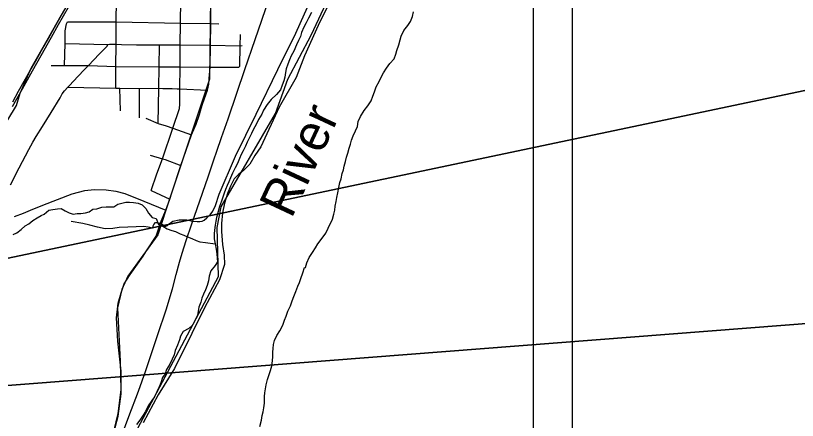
# Model space of a CAD drawing. Extents: x 0 to 34, y 0 to 22.
# Drawn here: x 7.567 to 9.58, y 17.57 to 18.613 of the extents above; entities that cross this region are included whole.
import ezdxf

# ---------------------------------------------------------------- set-up
doc = ezdxf.new("R2010")
doc.units = 0
for name, color, linetype in [('Default', 7, 'Continuous'), ('GM_X_City_Street', 7, 'Continuous'), ('GM_X_Corporation', 7, 'Continuous'), ('GM_X_County_Road', 7, 'Continuous'), ('GM_X_Major_River', 7, 'Continuous'), ('GM_X_Major_River_Text', 7, 'Continuous'), ('GM_X_Minor_River', 7, 'Continuous'), ('GM_X_Rail_Line', 7, 'Continuous'), ('GM_X_State_Route', 7, 'Continuous'), ('SC_Shading1', 7, 'Continuous'), ('SH_Cut_Line', 7, 'Continuous'), ('SH_Data', 7, 'Continuous')]:
    doc.layers.add(name, color=color, linetype=linetype)

msp = doc.modelspace()

# ---------------------------------------------------------------- linework, layer by layer
at = {"layer": 'Default'}
for p, q in [((8.3275, 18.5623), (8.3826, 18.6786)), ((8.2682, 18.4486), (8.3275, 18.5623)), ((8.2362, 18.3605), (8.2682, 18.4486)), ((8.0958, 18.1203), (8.2362, 18.3605)), ((8.0861, 18.0665), (8.0958, 18.1203)), ((8.0891, 17.94), (8.0861, 18.0665)), ((7.9735, 17.7219), (8.0891, 17.94)), ((7.8637, 17.5167), (7.9735, 17.7219))]:
    msp.add_line(p, q, dxfattribs=at)
at = {"layer": 'GM_X_City_Street'}
for p, q in [((8.288, 18.5677), (8.3375, 18.6773)), ((7.8259, 18.5966), (7.8266, 18.6535)), ((7.991, 18.5935), (7.9925, 18.6522)), ((7.6945, 18.5732), (7.6974, 18.5917)), ((7.6974, 18.5917), (7.7, 18.5966)), ((7.7, 18.5966), (7.8259, 18.5966)), ((7.8253, 18.5395), (7.8259, 18.5966)), ((7.8259, 18.5966), (7.991, 18.5935)), ((7.9905, 18.537), (7.991, 18.5935)), ((7.991, 18.5935), (8.0694, 18.5927)), ((8.0694, 18.5927), (8.0897, 18.5919)), ((7.6943, 18.5406), (7.6945, 18.5732)), ((8.2419, 18.4737), (8.288, 18.5677)), ((8.1454, 18.5352), (8.1456, 18.5644)), ((7.6922, 18.4838), (7.6943, 18.5406)), ((7.6943, 18.5406), (7.7683, 18.5393)), ((7.7683, 18.5393), (7.8045, 18.5385)), ((7.8246, 18.4817), (7.8253, 18.5395)), ((7.9362, 18.4811), (7.9369, 18.5377)), ((7.9909, 18.5241), (7.9905, 18.537)), ((8.0684, 18.5365), (8.1454, 18.5352)), ((8.1445, 18.4827), (8.1454, 18.5352)), ((8.1454, 18.5352), (8.1506, 18.5356)), ((7.9901, 18.4808), (7.9909, 18.5241)), ((7.658, 18.484), (7.6922, 18.4838)), ((7.6922, 18.4838), (7.7541, 18.4838)), ((7.7541, 18.4838), (7.8246, 18.4817)), ((7.8244, 18.4261), (7.8246, 18.4817)), ((7.8246, 18.4817), (7.9362, 18.4811)), ((7.9355, 18.4255), (7.9362, 18.4811)), ((7.9362, 18.4811), (7.9901, 18.4808)), ((7.9897, 18.424), (7.9901, 18.4808)), ((7.9901, 18.4808), (8.0675, 18.4799)), ((8.0675, 18.4799), (8.1417, 18.4799)), ((8.1417, 18.4799), (8.1445, 18.4827)), ((8.1865, 18.3591), (8.2419, 18.4737)), ((7.7011, 18.428), (7.8244, 18.4261)), ((7.8244, 18.4261), (7.835, 18.4259)), ((7.8364, 18.367), (7.835, 18.4259)), ((7.835, 18.4259), (7.8861, 18.4246)), ((7.8858, 18.3496), (7.8861, 18.4246)), ((7.8861, 18.4246), (7.9355, 18.4255)), ((7.9342, 18.3346), (7.9355, 18.4255)), ((7.9355, 18.4255), (7.9457, 18.4251)), ((7.9457, 18.4251), (7.9697, 18.4248)), ((7.9697, 18.4248), (7.983, 18.4243)), ((7.983, 18.4243), (7.9897, 18.424)), ((7.9893, 18.4014), (7.9897, 18.424)), ((7.9897, 18.424), (8.0606, 18.4209)), ((7.9884, 18.3732), (7.9895, 18.3841)), ((7.9895, 18.3841), (7.9893, 18.4014)), ((7.9712, 18.3226), (7.9884, 18.3732)), ((7.9018, 18.3487), (7.9342, 18.3346)), ((8.1332, 18.2503), (8.1865, 18.3591)), ((7.9342, 18.3346), (7.9543, 18.3286)), ((7.9543, 18.3286), (7.9712, 18.3226)), ((7.9446, 18.2437), (7.9712, 18.3226)), ((7.9712, 18.3226), (8.0201, 18.3053)), ((7.9131, 18.253), (7.9446, 18.2437)), ((7.9303, 18.2046), (7.9446, 18.2437)), ((7.9446, 18.2437), (7.9516, 18.2416)), ((8.0907, 18.1525), (8.1332, 18.2503)), ((7.9516, 18.2416), (7.9923, 18.2268)), ((7.9161, 18.1616), (7.9303, 18.2046)), ((7.9161, 18.1616), (7.9639, 18.1397)), ((8.0813, 18.1237), (8.0907, 18.1525)), ((8.0743, 18.1087), (8.0813, 18.1237)), ((8.0674, 18.0993), (8.0743, 18.1087)), ((7.7394, 18.0773), (7.7094, 18.0818)), ((7.9623, 18.0764), (7.972, 18.0832)), ((7.972, 18.0832), (7.9882, 18.0863)), ((7.9882, 18.0863), (8.0075, 18.0861)), ((8.0075, 18.0861), (8.0222, 18.0829)), ((8.0222, 18.0829), (8.0342, 18.0819)), ((8.0342, 18.0819), (8.0413, 18.082)), ((8.0413, 18.082), (8.047, 18.0832)), ((8.047, 18.0832), (8.0524, 18.0858)), ((8.0524, 18.0858), (8.0595, 18.0913)), ((8.0595, 18.0913), (8.0674, 18.0993)), ((7.7581, 18.0726), (7.7394, 18.0773)), ((7.7774, 18.0674), (7.7581, 18.0726)), ((7.7975, 18.0633), (7.7774, 18.0674)), ((7.8171, 18.0643), (7.7975, 18.0633)), ((7.8332, 18.0669), (7.8171, 18.0643)), ((7.8559, 18.0677), (7.8332, 18.0669)), ((7.8773, 18.0682), (7.8559, 18.0677)), ((7.8968, 18.0695), (7.8773, 18.0682)), ((7.908, 18.0677), (7.8968, 18.0695)), ((7.9198, 18.0648), (7.908, 18.0677)), ((7.9198, 18.0648), (7.9206, 18.0706)), ((7.9206, 18.0706), (7.9224, 18.0747)), ((7.9224, 18.0747), (7.9268, 18.0799)), ((7.9268, 18.0799), (7.9315, 18.0794)), ((7.9315, 18.0794), (7.9391, 18.0766)), ((7.9391, 18.0766), (7.9486, 18.0728)), ((7.9486, 18.0728), (7.9515, 18.0705)), ((7.9515, 18.0705), (7.954, 18.07)), ((7.954, 18.07), (7.9576, 18.0717)), ((7.9576, 18.0717), (7.9623, 18.0764))]:
    msp.add_line(p, q, dxfattribs=at)
at = {"layer": 'GM_X_Corporation'}
for p, q in [((8.3741, 18.645), (8.3461, 18.5875)), ((7.6479, 18.5494), (7.6845, 18.6148)), ((8.3461, 18.5875), (8.3111, 18.5089)), ((7.6063, 18.477), (7.6479, 18.5494)), ((8.3111, 18.5089), (8.2891, 18.4531)), ((7.5785, 18.4127), (7.6063, 18.477)), ((8.2891, 18.4531), (8.2457, 18.3765)), ((7.5689, 18.3809), (7.5785, 18.4127)), ((7.547, 18.3441), (7.5689, 18.3809)), ((8.2457, 18.3765), (8.1979, 18.2747)), ((8.1979, 18.2747), (8.1827, 18.2518)), ((8.1827, 18.2518), (8.1701, 18.2301)), ((8.1701, 18.2301), (8.1536, 18.2136)), ((8.1418, 18.2045), (8.1297, 18.1923)), ((8.1536, 18.2136), (8.1418, 18.2045)), ((8.1297, 18.1923), (8.1204, 18.1734)), ((8.1204, 18.1734), (8.1127, 18.1542)), ((8.1127, 18.1542), (8.1044, 18.1292)), ((8.1044, 18.1292), (8.0996, 18.1043)), ((8.0996, 18.1043), (8.0967, 18.0769)), ((8.0967, 18.0769), (8.0966, 18.0564)), ((8.0966, 18.0564), (8.0999, 18.023)), ((8.0999, 18.023), (8.1035, 17.9954)), ((8.1035, 17.9954), (8.1046, 17.9715)), ((8.1046, 17.9715), (8.0915, 17.9319)), ((8.0915, 17.9319), (8.0529, 17.86)), ((8.0529, 17.86), (8.0209, 17.7932)), ((8.0209, 17.7932), (7.9761, 17.7031)), ((7.9761, 17.7031), (7.9335, 17.6356)), ((7.9335, 17.6356), (7.8949, 17.5636))]:
    msp.add_line(p, q, dxfattribs=at)
at = {"layer": 'GM_X_County_Road'}
for p, q in [((8.0694, 18.5927), (8.0695, 18.6515)), ((8.0684, 18.5365), (8.0694, 18.5927)), ((7.7818, 18.513), (7.8023, 18.5341)), ((7.8023, 18.5341), (7.8045, 18.5385)), ((7.8045, 18.5385), (7.8082, 18.5395)), ((7.8082, 18.5395), (7.8101, 18.5395)), ((7.8101, 18.5395), (7.8253, 18.5395)), ((7.8253, 18.5395), (7.839, 18.5386)), ((7.839, 18.5386), (7.8779, 18.5377)), ((7.8779, 18.5377), (7.9369, 18.5377)), ((7.9369, 18.5377), (7.9905, 18.537)), ((7.9905, 18.537), (8.0684, 18.5365)), ((8.0675, 18.4799), (8.0684, 18.5365)), ((7.7541, 18.4838), (7.7818, 18.513)), ((7.7151, 18.4433), (7.7421, 18.4718)), ((7.7421, 18.4718), (7.7541, 18.4838)), ((8.0654, 18.4502), (8.0675, 18.4799)), ((8.0645, 18.4361), (8.0654, 18.4502)), ((7.6924, 18.4186), (7.7011, 18.428)), ((7.7011, 18.428), (7.7064, 18.4338)), ((7.7064, 18.4338), (7.7151, 18.4433)), ((8.0606, 18.4209), (8.0645, 18.4361)), ((7.6811, 18.4012), (7.6867, 18.4107)), ((7.6867, 18.4107), (7.6924, 18.4186)), ((8.0526, 18.3966), (8.0606, 18.4209)), ((7.658, 18.3633), (7.6811, 18.4012)), ((8.0445, 18.3734), (8.0493, 18.3873)), ((8.0493, 18.3873), (8.0526, 18.3966)), ((7.6358, 18.327), (7.658, 18.3633)), ((8.0402, 18.3581), (8.0445, 18.3734)), ((8.0315, 18.3331), (8.0402, 18.3581)), ((7.6198, 18.3015), (7.6358, 18.327)), ((8.0201, 18.3053), (8.0315, 18.3331)), ((7.9923, 18.2268), (8.0201, 18.3053)), ((7.6009, 18.2677), (7.6111, 18.2866)), ((7.6111, 18.2866), (7.6198, 18.3015)), ((7.5761, 18.2202), (7.6009, 18.2677)), ((7.9702, 18.1589), (7.9923, 18.2268)), ((7.5532, 18.1766), (7.5761, 18.2202)), ((7.7448, 18.1618), (7.7691, 18.1648)), ((7.7691, 18.1648), (7.7996, 18.164)), ((7.7996, 18.164), (7.8246, 18.1603)), ((7.6371, 18.124), (7.7122, 18.1537)), ((7.7122, 18.1537), (7.7448, 18.1618)), ((7.8246, 18.1603), (7.8484, 18.1539)), ((7.8484, 18.1539), (7.8966, 18.1349)), ((7.9639, 18.1397), (7.9702, 18.1589)), ((7.6046, 18.111), (7.6371, 18.124)), ((7.8966, 18.1349), (7.9535, 18.1115)), ((7.9535, 18.1115), (7.9639, 18.1397)), ((7.5641, 18.0953), (7.587, 18.1032)), ((7.587, 18.1032), (7.6046, 18.111)), ((7.9391, 18.0766), (7.9535, 18.1115)), ((7.9287, 18.044), (7.9378, 18.0725)), ((7.9378, 18.0725), (7.9391, 18.0766)), ((7.904, 18.0066), (7.9287, 18.044)), ((7.8952, 17.9932), (7.904, 18.0066)), ((7.862, 17.9456), (7.8952, 17.9932)), ((7.8463, 17.9214), (7.862, 17.9456)), ((7.8382, 17.8983), (7.8463, 17.9214)), ((7.831, 17.8719), (7.8382, 17.8983)), ((7.8265, 17.8336), (7.831, 17.8719)), ((7.8301, 17.7737), (7.8265, 17.8336)), ((7.8386, 17.6964), (7.8301, 17.7737)), ((7.8386, 17.638), (7.8386, 17.6964)), ((7.8307, 17.5807), (7.8386, 17.638)), ((7.8123, 17.5126), (7.8307, 17.5807))]:
    msp.add_line(p, q, dxfattribs=at)
at = {"layer": 'GM_X_Major_River'}
for p, q in [((8.3209, 18.6062), (8.3147, 18.5943)), ((8.3289, 18.6204), (8.3209, 18.6062)), ((8.584, 18.5979), (8.5887, 18.6105)), ((8.5887, 18.6105), (8.5915, 18.6227)), ((8.3147, 18.5943), (8.3092, 18.5832)), ((8.5663, 18.574), (8.5766, 18.5871)), ((8.5766, 18.5871), (8.584, 18.5979)), ((8.3034, 18.5694), (8.3002, 18.5591)), ((8.3092, 18.5832), (8.3034, 18.5694)), ((8.5601, 18.5595), (8.5663, 18.574)), ((8.2951, 18.5488), (8.2904, 18.5373)), ((8.3002, 18.5591), (8.2951, 18.5488)), ((8.5537, 18.537), (8.5573, 18.5499)), ((8.5573, 18.5499), (8.5601, 18.5595)), ((8.2904, 18.5373), (8.2831, 18.5209)), ((8.5487, 18.5228), (8.5537, 18.537)), ((8.2765, 18.509), (8.2725, 18.4983)), ((8.2831, 18.5209), (8.2765, 18.509)), ((8.5419, 18.5011), (8.5462, 18.5133)), ((8.5462, 18.5133), (8.5487, 18.5228)), ((8.2674, 18.4875), (8.2635, 18.4757)), ((8.2725, 18.4983), (8.2674, 18.4875)), ((8.5223, 18.4775), (8.5304, 18.4891)), ((8.5304, 18.4891), (8.5419, 18.5011)), ((8.2614, 18.4662), (8.2597, 18.4544)), ((8.2635, 18.4757), (8.2614, 18.4662)), ((8.5076, 18.4522), (8.5145, 18.4656)), ((8.5145, 18.4656), (8.5223, 18.4775)), ((8.2573, 18.4445), (8.2529, 18.4334)), ((8.2597, 18.4544), (8.2573, 18.4445)), ((8.5028, 18.4426), (8.5076, 18.4522)), ((8.2529, 18.4334), (8.2486, 18.4215)), ((8.4908, 18.4166), (8.4955, 18.4292)), ((8.4955, 18.4292), (8.5028, 18.4426)), ((8.2382, 18.4092), (8.2252, 18.3968)), ((8.2486, 18.4215), (8.2382, 18.4092)), ((8.4822, 18.3933), (8.4869, 18.4055)), ((8.4869, 18.4055), (8.4908, 18.4166)), ((8.2145, 18.3837), (8.2049, 18.3691)), ((8.2252, 18.3968), (8.2145, 18.3837)), ((8.4737, 18.3802), (8.4822, 18.3933)), ((8.2049, 18.3691), (8.2009, 18.3591)), ((8.4553, 18.3529), (8.4641, 18.3679)), ((8.4641, 18.3679), (8.4737, 18.3802)), ((8.1921, 18.3449), (8.187, 18.3334)), ((8.2009, 18.3591), (8.1921, 18.3449)), ((8.4491, 18.3395), (8.4553, 18.3529)), ((8.187, 18.3334), (8.1782, 18.3181)), ((8.4423, 18.3159), (8.4471, 18.3266)), ((8.4471, 18.3266), (8.4491, 18.3395)), ((8.1738, 18.3085), (8.1633, 18.2863)), ((8.1782, 18.3181), (8.1738, 18.3085)), ((8.4365, 18.3025), (8.4423, 18.3159)), ((8.1633, 18.2863), (8.1589, 18.2764)), ((8.4294, 18.2818), (8.4318, 18.2914)), ((8.4318, 18.2914), (8.4365, 18.3025)), ((8.1531, 18.2645), (8.148, 18.2545)), ((8.1589, 18.2764), (8.1531, 18.2645)), ((8.4222, 18.2582), (8.4261, 18.2715)), ((8.4261, 18.2715), (8.4294, 18.2818)), ((8.1436, 18.2446), (8.1382, 18.2315)), ((8.148, 18.2545), (8.1436, 18.2446)), ((8.4162, 18.2368), (8.419, 18.2478)), ((8.419, 18.2478), (8.4222, 18.2582)), ((8.1382, 18.2315), (8.1319, 18.2208)), ((8.4109, 18.215), (8.413, 18.2246)), ((8.413, 18.2246), (8.4162, 18.2368)), ((8.1257, 18.207), (8.1199, 18.1944)), ((8.1319, 18.2208), (8.1257, 18.207)), ((8.4049, 18.1925), (8.4081, 18.2055)), ((8.4081, 18.2055), (8.4109, 18.215)), ((8.1156, 18.184), (8.1116, 18.1745)), ((8.1199, 18.1944), (8.1156, 18.184)), ((8.3996, 18.17), (8.402, 18.183)), ((8.402, 18.183), (8.4049, 18.1925)), ((8.1076, 18.1649), (8.104, 18.155)), ((8.1116, 18.1745), (8.1076, 18.1649)), ((8.3965, 18.1559), (8.3996, 18.17)), ((8.104, 18.155), (8.0968, 18.1343)), ((8.392, 18.1334), (8.3941, 18.1437)), ((8.3941, 18.1437), (8.3965, 18.1559)), ((8.0968, 18.1343), (8.0917, 18.1209)), ((8.3886, 18.111), (8.3899, 18.1216)), ((8.3899, 18.1216), (8.392, 18.1334)), ((8.0882, 18.1076), (8.0843, 18.0927)), ((8.0917, 18.1209), (8.0882, 18.1076)), ((8.3865, 18.1014), (8.3886, 18.111)), ((8.0822, 18.0832), (8.0805, 18.0729)), ((8.0843, 18.0927), (8.0822, 18.0832)), ((8.3721, 18.0651), (8.383, 18.0881)), ((8.383, 18.0881), (8.3865, 18.1014)), ((8.0805, 18.0729), (8.0785, 18.0599)), ((8.3655, 18.052), (8.3721, 18.0651)), ((8.0785, 18.0599), (8.0779, 18.0504)), ((8.0779, 18.0504), (8.0782, 18.0372)), ((8.3566, 18.039), (8.3655, 18.052)), ((8.0782, 18.0372), (8.0807, 18.0243)), ((8.0807, 18.0243), (8.0828, 18.0107)), ((8.3393, 18.0147), (8.3452, 18.0243)), ((8.3452, 18.0243), (8.3566, 18.039)), ((8.0828, 18.0107), (8.0853, 17.9989)), ((8.3231, 17.9893), (8.3312, 18.0024)), ((8.3312, 18.0024), (8.3393, 18.0147)), ((8.0853, 17.9989), (8.0859, 17.9879)), ((8.0859, 17.9879), (8.0865, 17.9781)), ((8.3165, 17.9756), (8.3231, 17.9893)), ((8.081, 17.9685), (8.0698, 17.9553)), ((8.0865, 17.9781), (8.081, 17.9685)), ((8.3064, 17.9499), (8.3111, 17.9637)), ((8.3111, 17.9637), (8.313, 17.9637)), ((8.313, 17.9637), (8.3165, 17.9756)), ((8.0656, 17.9416), (8.0631, 17.9294)), ((8.0698, 17.9553), (8.0656, 17.9416)), ((8.3014, 17.935), (8.3064, 17.9499)), ((8.0631, 17.9294), (8.06, 17.9168)), ((8.2934, 17.9155), (8.2981, 17.9251)), ((8.2981, 17.9251), (8.3014, 17.935)), ((8.0556, 17.9057), (8.0505, 17.8953)), ((8.06, 17.9168), (8.0556, 17.9057)), ((8.2833, 17.8891), (8.2883, 17.9021)), ((8.2883, 17.9021), (8.2934, 17.9155)), ((8.0465, 17.885), (8.0433, 17.8743)), ((8.0505, 17.8953), (8.0465, 17.885)), ((8.2789, 17.8776), (8.2833, 17.8891)), ((8.039, 17.8617), (8.0369, 17.8514)), ((8.0433, 17.8743), (8.039, 17.8617)), ((8.2681, 17.8508), (8.2743, 17.8646)), ((8.2743, 17.8646), (8.2789, 17.8776)), ((8.0369, 17.8514), (8.0349, 17.8396)), ((8.2634, 17.8378), (8.2681, 17.8508)), ((8.0286, 17.8273), (8.0219, 17.8154)), ((8.0349, 17.8396), (8.0286, 17.8273)), ((8.2551, 17.8149), (8.2594, 17.8275)), ((8.2594, 17.8275), (8.2634, 17.8378)), ((8.0124, 17.8061), (7.9985, 17.799)), ((8.0219, 17.8154), (8.0124, 17.8061)), ((8.2393, 17.788), (8.2474, 17.8003)), ((8.2474, 17.8003), (8.2551, 17.8149)), ((7.9915, 17.7867), (7.9887, 17.7768)), ((7.9985, 17.799), (7.9915, 17.7867)), ((8.2331, 17.7753), (8.2393, 17.788)), ((7.9836, 17.7638), (7.9778, 17.7496)), ((7.9887, 17.7768), (7.9836, 17.7638)), ((8.2297, 17.7551), (8.231, 17.7654)), ((8.231, 17.7654), (8.2331, 17.7753)), ((7.9778, 17.7496), (7.975, 17.7385)), ((8.2293, 17.7346), (8.2295, 17.7452)), ((8.2295, 17.7452), (8.2297, 17.7551)), ((7.9695, 17.727), (7.9637, 17.7144)), ((7.975, 17.7385), (7.9695, 17.727)), ((8.2267, 17.7106), (8.228, 17.7232)), ((8.228, 17.7232), (8.2293, 17.7346)), ((7.9549, 17.7009), (7.952, 17.6899)), ((7.9637, 17.7144), (7.9549, 17.7009)), ((8.2228, 17.6984), (8.2267, 17.7106)), ((7.9454, 17.6799), (7.9403, 17.6668)), ((7.952, 17.6899), (7.9454, 17.6799)), ((8.2153, 17.6747), (8.2185, 17.6854)), ((8.2185, 17.6854), (8.2228, 17.6984)), ((7.9403, 17.6668), (7.936, 17.6565)), ((8.2104, 17.6507), (8.2121, 17.6617)), ((8.2121, 17.6617), (8.2153, 17.6747)), ((7.9302, 17.6431), (7.9241, 17.6305)), ((7.936, 17.6565), (7.9302, 17.6431)), ((8.2081, 17.6312), (8.2087, 17.6407)), ((8.2087, 17.6407), (8.2104, 17.6507)), ((7.9175, 17.6208), (7.9085, 17.607)), ((7.9241, 17.6305), (7.9175, 17.6208)), ((8.2077, 17.6141), (8.2081, 17.6312)), ((7.9085, 17.607), (7.9008, 17.5928)), ((8.2039, 17.592), (8.2064, 17.6016)), ((8.2064, 17.6016), (8.2077, 17.6141)), ((7.8949, 17.5831), (7.8868, 17.5701)), ((7.9008, 17.5928), (7.8949, 17.5831)), ((8.1998, 17.5703), (8.2018, 17.5825)), ((8.2018, 17.5825), (8.2039, 17.592)), ((7.8868, 17.5701), (7.8779, 17.5589)), ((8.1955, 17.5542), (8.1998, 17.5703))]:
    msp.add_line(p, q, dxfattribs=at)
at = {"layer": 'GM_X_Minor_River'}
for p, q in [((7.82, 18.1201), (7.8301, 18.1265)), ((7.8301, 18.1265), (7.8406, 18.1298)), ((7.8406, 18.1298), (7.8504, 18.1316)), ((7.8504, 18.1316), (7.8603, 18.1323)), ((7.8603, 18.1323), (7.8706, 18.1314)), ((7.8706, 18.1314), (7.8824, 18.1291)), ((7.8824, 18.1291), (7.8924, 18.1251)), ((7.8924, 18.1251), (7.9018, 18.1155)), ((7.6406, 18.1011), (7.6526, 18.1111)), ((7.6526, 18.1111), (7.6628, 18.1129)), ((7.6628, 18.1129), (7.6749, 18.1147)), ((7.6749, 18.1147), (7.6844, 18.1153)), ((7.6844, 18.1153), (7.6945, 18.1095)), ((7.6945, 18.1095), (7.7049, 18.1041)), ((7.7049, 18.1041), (7.7152, 18.1009)), ((7.7152, 18.1009), (7.725, 18.1027)), ((7.725, 18.1027), (7.7349, 18.103)), ((7.7349, 18.103), (7.7463, 18.1048)), ((7.7463, 18.1048), (7.7561, 18.107)), ((7.7561, 18.107), (7.7658, 18.1141)), ((7.7658, 18.1141), (7.776, 18.1148)), ((7.776, 18.1148), (7.7888, 18.1193)), ((7.7888, 18.1193), (7.7998, 18.12)), ((7.7998, 18.12), (7.8101, 18.1203)), ((7.8101, 18.1203), (7.82, 18.1201)), ((7.9018, 18.1155), (7.9089, 18.1039)), ((7.9089, 18.1039), (7.918, 18.0927)), ((7.6011, 18.0762), (7.6112, 18.0844)), ((7.6112, 18.0844), (7.622, 18.0912)), ((7.622, 18.0912), (7.6325, 18.0976)), ((7.6325, 18.0976), (7.6406, 18.1011)), ((7.918, 18.0927), (7.9291, 18.09)), ((7.9291, 18.09), (7.9344, 18.0741)), ((7.5702, 18.0529), (7.5806, 18.0619)), ((7.5806, 18.0619), (7.5914, 18.0706)), ((7.5914, 18.0706), (7.6011, 18.0762)), ((7.9344, 18.0741), (7.946, 18.0699)), ((7.946, 18.0699), (7.9572, 18.0633)), ((7.9572, 18.0633), (7.9687, 18.0587)), ((7.5604, 18.0484), (7.5702, 18.0529)), ((7.9687, 18.0587), (7.9786, 18.0563)), ((7.9786, 18.0563), (7.9902, 18.0505)), ((7.9902, 18.0505), (8.0001, 18.0473)), ((8.0001, 18.0473), (8.0098, 18.043)), ((8.0098, 18.043), (8.0202, 18.038)), ((8.0202, 18.038), (8.0313, 18.0333)), ((8.0313, 18.0333), (8.0409, 18.0294)), ((8.0409, 18.0294), (8.0554, 18.0283)), ((8.0554, 18.0283), (8.0807, 18.0243))]:
    msp.add_line(p, q, dxfattribs=at)
at = {"layer": 'GM_X_Rail_Line'}
for p, q in [((8.0696, 18.7536), (8.0661, 18.4488)), ((8.1838, 18.551), (8.2188, 18.654)), ((8.157, 18.4742), (8.1838, 18.551)), ((8.1362, 18.4129), (8.157, 18.4742)), ((8.0661, 18.4488), (7.9534, 18.1115)), ((8.1137, 18.3468), (8.1362, 18.4129)), ((8.0972, 18.2988), (8.1137, 18.3468)), ((8.0852, 18.2632), (8.0972, 18.2988)), ((8.0776, 18.2412), (8.0852, 18.2632)), ((8.0623, 18.1971), (8.0776, 18.2412)), ((8.0344, 18.1156), (8.0623, 18.1971)), ((7.9534, 18.1115), (7.9326, 18.048)), ((8.0209, 18.0759), (8.0344, 18.1156)), ((8.0062, 18.0333), (8.0209, 18.0759)), ((7.9326, 18.048), (7.856, 17.9409)), ((7.9956, 18.0008), (8.0062, 18.0333)), ((7.9889, 17.9776), (7.9956, 18.0008)), ((7.9803, 17.9458), (7.9889, 17.9776)), ((7.856, 17.9409), (7.8406, 17.9066)), ((7.9704, 17.9083), (7.9803, 17.9458)), ((7.8406, 17.9066), (7.8292, 17.8596)), ((7.9547, 17.8541), (7.9704, 17.9083)), ((7.8292, 17.8596), (7.836, 17.7226)), ((7.9334, 17.7906), (7.9547, 17.8541)), ((7.9178, 17.7443), (7.9334, 17.7906)), ((7.9021, 17.6986), (7.9178, 17.7443)), ((7.836, 17.7226), (7.8379, 17.6484)), ((7.883, 17.6451), (7.9021, 17.6986)), ((7.8379, 17.6484), (7.8303, 17.587)), ((7.8581, 17.5794), (7.883, 17.6451)), ((7.8303, 17.587), (7.8145, 17.5226)), ((7.8382, 17.5267), (7.8581, 17.5794))]:
    msp.add_line(p, q, dxfattribs=at)
at = {"layer": 'GM_X_State_Route'}
for p, q in [((7.6775, 18.5894), (7.7031, 18.6347)), ((7.6815, 18.6075), (7.6967, 18.6342)), ((7.667, 18.5818), (7.6815, 18.6075)), ((7.659, 18.5567), (7.6775, 18.5894)), ((7.6522, 18.5554), (7.667, 18.5818)), ((7.6327, 18.5102), (7.659, 18.5567)), ((7.6337, 18.5229), (7.6522, 18.5554)), ((7.6103, 18.4705), (7.6327, 18.5102)), ((7.619, 18.4965), (7.6337, 18.5229)), ((7.6036, 18.4694), (7.619, 18.4965)), ((7.5843, 18.4244), (7.6103, 18.4705)), ((7.589, 18.4435), (7.6036, 18.4694)), ((7.5583, 18.3785), (7.5843, 18.4244)), ((7.5745, 18.4181), (7.589, 18.4435)), ((7.5592, 18.3909), (7.5745, 18.4181))]:
    msp.add_line(p, q, dxfattribs=at)
at = {"layer": 'SC_Shading1'}
msp.add_lwpolyline([(10.224, 18.5508), (10.224, 17.8673), (5.0783, 17.4676)], close=True, dxfattribs=at)
at = {"layer": 'SH_Cut_Line'}
for p, q in [((8.3275, 18.5623), (8.3826, 18.6786)), ((8.2682, 18.4486), (8.3275, 18.5623)), ((8.2362, 18.3605), (8.2682, 18.4486)), ((8.0958, 18.1203), (8.2362, 18.3605)), ((8.0861, 18.0665), (8.0958, 18.1203)), ((8.0891, 17.94), (8.0861, 18.0665)), ((7.9735, 17.7219), (8.0891, 17.94)), ((7.8637, 17.5167), (7.9735, 17.7219))]:
    msp.add_line(p, q, dxfattribs=at)
at = {"layer": 'SH_Data'}
for p, q in [((9, 21), (9, 14)), ((8.9, 20.9), (8.9, 14.1))]:
    msp.add_line(p, q, dxfattribs=at)
msp.add_lwpolyline([(10.224, 18.5508), (5.0783, 17.4676), (10.224, 17.8673)], dxfattribs=at)

# ---------------------------------------------------------------- texts
at = {"layer": 'GM_X_Major_River_Text'}
msp.add_text('River', height=0.09475, rotation=64.959, dxfattribs=at).set_placement((8.2771, 18.0874))

doc.saveas('drawing.dxf')
